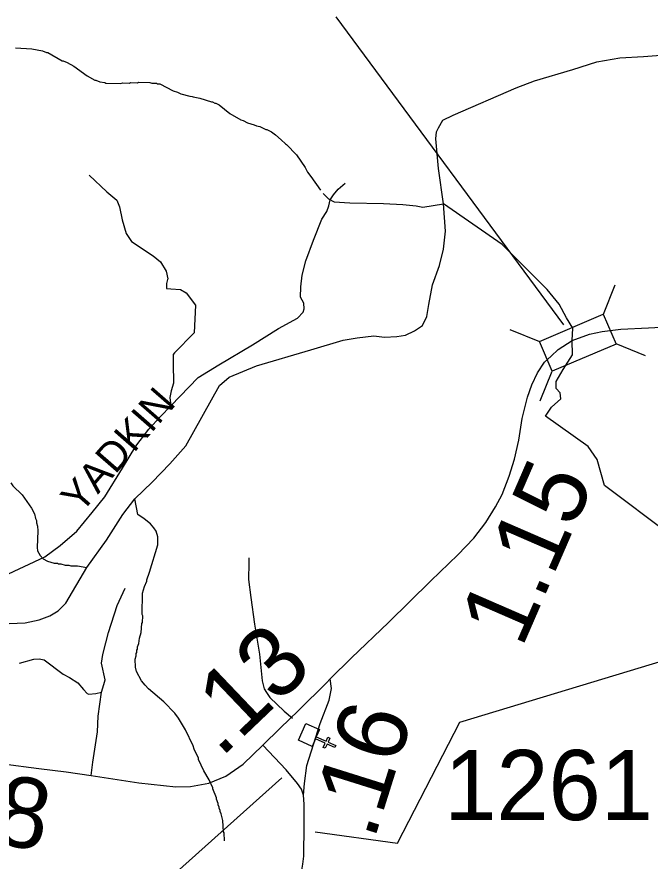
# Model space of a CAD drawing. Extents: x 1248089 to 1457196, y 820910 to 988753.
# Drawn here: x 1303139 to 1307656, y 857039 to 863059 of the extents above; entities that cross this region are included whole.
import ezdxf

# ---------------------------------------------------------------- set-up
doc = ezdxf.new("R2010")
doc.units = 0
for name, color, linetype in [('Exist Cultural Church CELL', 7, 'Continuous'), ('Exist Hydrographic Creek Single Shore', 7, 'Continuous'), ('Exist Hydrographic Misc Water Feature', 7, 'Continuous'), ('Exist Hydrographic River Shore', 7, 'Continuous'), ('Exist Hydrographic River Shore Label', 7, 'Continuous'), ('Exist Road Non-System Type 51', 7, 'Continuous'), ('Exist Road Primary NC Attributed', 7, 'Continuous'), ('Exist Road Primary NC Structure Standard Bridge CELL', 7, 'Continuous'), ('Exist Road Primary NC Structure Standard Bridge Number Label', 7, 'Continuous'), ('Exist Road Secondary Type 51 Attributed', 7, 'Continuous'), ('Prop CMT Slope Fill', 7, 'Continuous'), ('Prop GRAU CAT1 Cell', 7, 'Continuous'), ('Prop Lane Lines', 7, 'Continuous')]:
    doc.layers.add(name, color=color, linetype=linetype)

msp = doc.modelspace()

# ---------------------------------------------------------------- linework, layer by layer
at = {"layer": 'Exist Cultural Church CELL'}
msp.add_lwpolyline([(1305298, 857976.7), (1305275, 857924.7), (1305344.5, 857893.7), (1305357.5, 857922.9), (1305372.1, 857916.5), (1305359.1, 857887.2), (1305414.1, 857862.8), (1305407.6, 857848.1), (1305352.6, 857872.6), (1305339.6, 857843.3), (1305325, 857849.8), (1305338, 857879.1), (1305268.4, 857910), (1305244.9, 857857.4), (1305147.6, 857900.7), (1305200.7, 858020)], close=True, dxfattribs=at)
at = {"layer": 'Exist Hydrographic Creek Single Shore'}
for points in [[(1307100.7, 860752.1), (1307104.1, 860839.3), (1307061, 860913), (1307007.6, 861009.6), (1306921.2, 861115.4), (1306601.9, 861434.9), (1306182.9, 861726.5)], [(1306909.5, 860210.9), (1306953.5, 860277), (1307019.5, 860334.6), (1307014.4, 860378.6), (1306987.3, 860409.1), (1306985.6, 860458.2), (1307035.6, 860544.6), (1307101.6, 860648.8), (1307100.7, 860752.1)], [(1307849.8, 859335.3), (1307798.5, 859366.7), (1307331.5, 859717.4), (1307277.6, 859902.4), (1307213.5, 859995.5), (1306909.5, 860210.9)]]:
    msp.add_lwpolyline(points, dxfattribs=at)
at = {"layer": 'Exist Hydrographic Misc Water Feature'}
for points in [[(1303128.4, 862837.7), (1303246.2, 862831), (1303321.9, 862817.2), (1303351.6, 862804.5), (1303359.6, 862804.3), (1303462.3, 862745.9), (1303470.3, 862745.8), (1303498, 862733.1), (1303545.5, 862707.9), (1303639.9, 862639.8), (1303695.3, 862608.5), (1303703.3, 862608.3), (1303730.9, 862595.7), (1303766.8, 862590.9), (1303774.7, 862586.7), (1303878.7, 862584.2), (1303894.8, 862587.8), (1303942.8, 862586.7), (1303950.9, 862590.4), (1303998.8, 862589.4), (1304006.9, 862593.2), (1304086.9, 862591.3), (1304102.8, 862587), (1304134.8, 862586.1), (1304142.7, 862582), (1304158.7, 862581.6), (1304253.5, 862531.4), (1304285.3, 862522.7), (1304309.1, 862510.2), (1304372.6, 862492.6), (1304388.6, 862492.2), (1304396.5, 862488), (1304444.4, 862479), (1304527.8, 862453), (1304535.8, 862452.9), (1304551.6, 862444.4), (1304559.5, 862444.2), (1304583.3, 862431.7), (1304657.9, 862370), (1304736.9, 862324.1), (1304752.8, 862319.8), (1304784.4, 862303.1), (1304832.2, 862289.9), (1304848, 862281.5), (1304871.8, 862276.9), (1304915.3, 862256), (1304923.3, 862255.8), (1304955, 862239), (1304984.5, 862218.4), (1305025.7, 862183.4), (1305055.1, 862152.7), (1305063, 862148.6), (1305133.3, 862074.8), (1305195.3, 861985.4), (1305212.5, 861953), (1305235.7, 861920.6), (1305306.3, 861822.9)], [(1305323.5, 861799.3), (1305362.2, 861761.5), (1305403.7, 861740.6), (1305515.6, 861733.9), (1305755.5, 861728.4), (1305891.4, 861721.1), (1305987.1, 861711), (1306034.9, 861701.9), (1306182.9, 861726.5)], [(1303096.2, 859736.2), (1303109.7, 859714.7), (1303176.3, 859651.1), (1303244.1, 859555.6), (1303265.3, 859515.1), (1303272.5, 859482.9), (1303280.1, 859466.7), (1303279.8, 859450.7), (1303287.2, 859426.6), (1303288.5, 859394.6), (1303283.8, 859274.7), (1303287.3, 859250.6), (1303304.5, 859218.2), (1303328, 859193.7), (1303357.6, 859176.9), (1303405.3, 859163.9), (1303429.3, 859163.3), (1303437.2, 859159.1), (1303453.2, 859158.7), (1303485, 859150), (1303509, 859149.4), (1303524.9, 859145.1), (1303572.8, 859143.9), (1303637.8, 859133.7)], [(1304085.4, 859098.8), (1304144.3, 859294.5), (1304145.7, 859350.5), (1304132.5, 859390.8), (1304117, 859415.1), (1304091.7, 859443.7), (1304046.5, 859480.8), (1304001.2, 859511.8), (1303979.9, 859621.3)], [(1304620.7, 857183.7), (1304621.2, 857207.7), (1304617.4, 857215.8), (1304617.9, 857239.8), (1304614.1, 857247.9), (1304607.9, 857328), (1304597, 857376.2), (1304589.4, 857392.4), (1304589.6, 857400.4), (1304581.9, 857416.6), (1304582.1, 857424.6), (1304574.4, 857440.8), (1304574.6, 857448.8), (1304563.3, 857481), (1304563.5, 857489), (1304537, 857553.6), (1304537.2, 857561.6), (1304510.4, 857618.2), (1304471.9, 857683.1), (1304433.8, 857764), (1304434, 857772), (1304403.4, 857836.7), (1304395.9, 857860.9), (1304342.5, 857974.1), (1304292.4, 858057.3), (1304265.2, 858093.9), (1304187.1, 858175.7), (1304079.1, 858268.2), (1304055.6, 858292.8), (1304028.5, 858325.4), (1303991.9, 858390.3), (1303984.6, 858422.4), (1303983.9, 858478.4), (1303990.4, 858502.3), (1303990.7, 858518.3), (1303994.9, 858526.2), (1303995.3, 858542.2), (1303999.4, 858550), (1303999.9, 858566), (1304008.4, 858589.8), (1304013.3, 858629.7), (1304026.2, 858669.4), (1304031.6, 858733.3), (1304035.8, 858741.2), (1304036.9, 858789.1), (1304033.1, 858797.2), (1304036.6, 858949.1), (1304049.6, 858996.8), (1304066.5, 859036.4), (1304066.7, 859044.4), (1304085.4, 859098.8)]]:
    msp.add_lwpolyline(points, dxfattribs=at)
at = {"layer": 'Exist Hydrographic River Shore'}
for points in [[(1306182.9, 861726.5), (1306147.9, 861979), (1306128, 862188.7), (1306133, 862238.6), (1306147.9, 862268.6), (1306177.9, 862323.5), (1306252.7, 862358.5), (1306701.7, 862553.2), (1306831.4, 862603.1), (1307105.8, 862683), (1307275.4, 862737.9), (1307440, 862767.8), (1307609.6, 862777.8), (1307764.3, 862787.8)], [(1303084.3, 858733.8), (1303199.1, 858738.8), (1303298.9, 858758.7), (1303373.7, 858788.7), (1303433.6, 858823.6), (1303488.4, 858878.5), (1303637.8, 859133.7), (1303777.8, 859327.9), (1303895.1, 859511.4), (1303979.9, 859621.3), (1304104.6, 859741.1), (1304229.4, 859870.9), (1304344.1, 860000.7), (1304583.6, 860430), (1304653.4, 860489.9), (1304848, 860569.8), (1305237.1, 860684.6), (1305466.6, 860754.5), (1305566.3, 860769.5), (1305686.1, 860784.5), (1305760.9, 860774.5), (1305850.7, 860779.5), (1305910.6, 860789.5), (1305975.4, 860819.4), (1306033.3, 860857.9), (1306063.2, 860922.8), (1306078.2, 861007.6), (1306103.1, 861147.4), (1306153, 861287.2), (1306182.9, 861402), (1306197.9, 861531.8), (1306182.9, 861726.5)]]:
    msp.add_lwpolyline(points, dxfattribs=at)
at = {"layer": 'Exist Road Non-System Type 51'}
for points in [[(1303655.2, 861931), (1303781.6, 861811.2), (1303851.4, 861751.3), (1303871.4, 861704.7), (1303891.4, 861611.5), (1303918, 861515), (1303957.9, 861458.4), (1304110.9, 861355.3), (1304164.1, 861312), (1304204, 861245.4), (1304217.3, 861192.2), (1304214, 861185.5), (1304207.3, 861158.9), (1304207.3, 861122.3), (1304237.2, 861119), (1304307.1, 861115.6), (1304347, 861092.3), (1304413.5, 861002.5), (1304403.5, 860806.1), (1304264.2, 860664.5), (1304254.2, 860651.2), (1304254.2, 860587.9), (1304257.6, 860448.2), (1304240.9, 860391.6), (1304231, 860345), (1304237.5, 860285.5)], [(1304237.5, 860285.5), (1304433.7, 860488.5), (1304580.1, 860578.4), (1304819.5, 860721.5), (1305005.8, 860838), (1305142.2, 860911.2), (1305182.1, 860954.4), (1305188.7, 860977.7), (1305185.4, 861017.7), (1305162.1, 861060.9), (1305165.1, 861133), (1305175.1, 861216.2), (1305201.7, 861319.4), (1305254.9, 861465.9), (1305314.8, 861615.6), (1305350.9, 861671), (1305364.2, 861710.9), (1305374.2, 861754.2), (1305397.5, 861790.8), (1305430.7, 861830.7), (1305480.6, 861874)], [(1302473.4, 859004.9), (1302566.1, 858976.6), (1302775.6, 859016.6), (1302961.9, 859046.5), (1303045, 859069.8), (1303337.7, 859209.6), (1303447.4, 859289.5), (1303567.2, 859392.6), (1303676.9, 859525.8), (1303766.7, 859635.6), (1303893.1, 859842), (1303988.4, 859997.1), (1304081.6, 860120.3), (1304164.7, 860210.1), (1304237.5, 860285.5)], [(1304793, 859202.3), (1304794.3, 859166.3), (1304791.9, 859048.2), (1304807.3, 858917.9), (1304835.6, 858729.2), (1304869.3, 858514.4), (1304889.5, 858323.9), (1304902.3, 858267.6), (1304919.8, 858241.2), (1304943.1, 858204.7), (1305045.2, 858108.6), (1305104.3, 858059.4)], [(1303742.5, 858243.4), (1303760.5, 858297.6), (1303768.5, 858331.8), (1303742.5, 858450.2), (1303752.5, 858512.4), (1303774.6, 858594.8), (1303792.6, 858669), (1303854.8, 858862.6), (1303913, 858985.1)], [(1303157, 858449.8), (1303259.3, 858479.9), (1303297.4, 858481.9), (1303333.5, 858473.9), (1303470, 858371.5), (1303514.1, 858347.4), (1303574.3, 858311.3), (1303614.4, 858263.1), (1303640.5, 858235), (1303652.5, 858228.9), (1303702.7, 858233), (1303742.5, 858243.4)], [(1303669.9, 857650.1), (1303682.3, 857745.5), (1303714.4, 857960.3), (1303718.4, 858072.8), (1303742.5, 858243.4)]]:
    msp.add_lwpolyline(points, dxfattribs=at)
at = {"layer": 'Exist Road Primary NC Attributed'}
for points in [[(1307100.7, 860752.1), (1307223.1, 860796.6), (1307314.4, 860814.9), (1307446.8, 860831.6), (1307644.7, 860840.8), (1307953.8, 860857.5), (1308085.5, 860862.1), (1308220.9, 860883.4), (1308647.2, 861009.8), (1309092.4, 861143.6), (1309388.3, 861225.3)], [(1305374.1, 858337.6), (1305526.4, 858488.4), (1305789.7, 858739.8), (1306092.1, 859037.6), (1306283.9, 859223.4), (1306399.1, 859343), (1306484.3, 859452.6), (1306552.9, 859565.4), (1306600, 859653.7), (1306651.3, 859783.7), (1306689.4, 859905.5), (1306719.8, 860039.6), (1306744.2, 860195), (1306782.2, 860347.9), (1306812.6, 860436.3), (1306852.2, 860521.6), (1306902.4, 860596.2), (1306951.1, 860640.4), (1306999.9, 860687.6), (1307100.7, 860752.1)], [(1301009.3, 858378.1), (1301184.2, 858368.4), (1301334.9, 858333.3), (1301549.5, 858252.6), (1302022.9, 858080.4), (1302597.6, 857869.1), (1302909.7, 857756.3), (1303042.7, 857732.3), (1303296.9, 857698.8), (1303490.2, 857674.4), (1303669.9, 857650.1), (1304010, 857596.9), (1304273.4, 857569.5), (1304376.9, 857571), (1304507.8, 857593.9), (1304630.5, 857645.6), (1304753.8, 857731), (1304893.9, 857865)], [(1304893.9, 857865), (1305017.2, 857988.1), (1305148.1, 858113.1), (1305347.5, 858311.1), (1305374.1, 858337.6)]]:
    msp.add_lwpolyline(points, dxfattribs=at)
at = {"layer": 'Exist Road Primary NC Structure Standard Bridge CELL'}
for p, q in [((1307322.9, 860938.1), (1307407.3, 861148.2)), ((1306656.4, 860829), (1306866.5, 860744.6)), ((1307411.7, 860729.9), (1307621.7, 860645.5)), ((1306872.9, 860321.5), (1306957.3, 860531.6))]:
    msp.add_line(p, q, dxfattribs=at)
msp.add_lwpolyline([(1306866.5, 860744.6), (1307322.5, 860939.1), (1307413.3, 860726.1), (1306957.3, 860531.6)], close=True, dxfattribs=at)
at = {"layer": 'Exist Road Primary NC Structure Standard Bridge Number Label'}
msp.add_line((1307041.1, 860863.2), (1305416.7, 863059.1), dxfattribs=at)
at = {"layer": 'Exist Road Secondary Type 51 Attributed'}
for points in [[(1305184.4, 857509), (1305191.5, 857591.3), (1305208.7, 857720.2), (1305303.1, 858020.8), (1305366, 858186.8), (1305383.2, 858269.8), (1305374.1, 858337.6)], [(1305184.4, 857509), (1305168.9, 857551.5), (1305140.6, 857592.8), (1305059.4, 857689.6), (1304893.9, 857865)], [(1305168.9, 856959.2), (1305179.2, 857016), (1305186.9, 857075.3), (1305188.2, 857294.6), (1305188.3, 857445.8), (1305184.4, 857509)]]:
    msp.add_lwpolyline(points, dxfattribs=at)
at = {"layer": 'Prop Lane Lines'}
msp.add_line((1305029.7, 857633.7), (1303997.6, 856710.7), dxfattribs=at)
msp.add_lwpolyline([(1305267.9, 857246.6), (1305853.5, 857167.2), (1306300.1, 858030.7), (1309386.5, 858963.6)], dxfattribs=at)

# ---------------------------------------------------------------- texts
at = {"layer": 'Exist Hydrographic River Shore Label'}
msp.add_text('YADKIN', height=210, rotation=48.88453, dxfattribs=at).set_placement((1303594, 859510.1))
at = {"layer": 'Prop CMT Slope Fill'}
for s, rotation, p in [('1.15', 66.51753, (1306740.5, 858550.7)), ('.13', 43.65859, (1304592.2, 857768.4)), ('.78', 349.77204, (1302411.5, 857271.1))]:
    msp.add_text(s, height=500, rotation=rotation, dxfattribs=at).set_placement(p)
at = {"layer": 'Prop GRAU CAT1 Cell'}
msp.add_text('.16', height=500, rotation=72.56571, dxfattribs=at).set_placement((1305686.5, 857180.6))
at = {"layer": 'Prop Lane Lines'}
msp.add_text('1261', height=500, dxfattribs=at).set_placement((1306188.4, 857331.5))

doc.saveas('drawing.dxf')
